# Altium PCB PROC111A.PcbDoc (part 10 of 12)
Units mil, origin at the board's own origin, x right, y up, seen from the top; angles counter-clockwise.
Board outline 7700 x 2300 mil, 6 copper layers (Top Layer, GND 1, SIG 1, SIG 2, GND 2, Bottom Layer), stack 61.062 mil thick; 841 components, 632 nets, 2914 pads, 1627 vias.
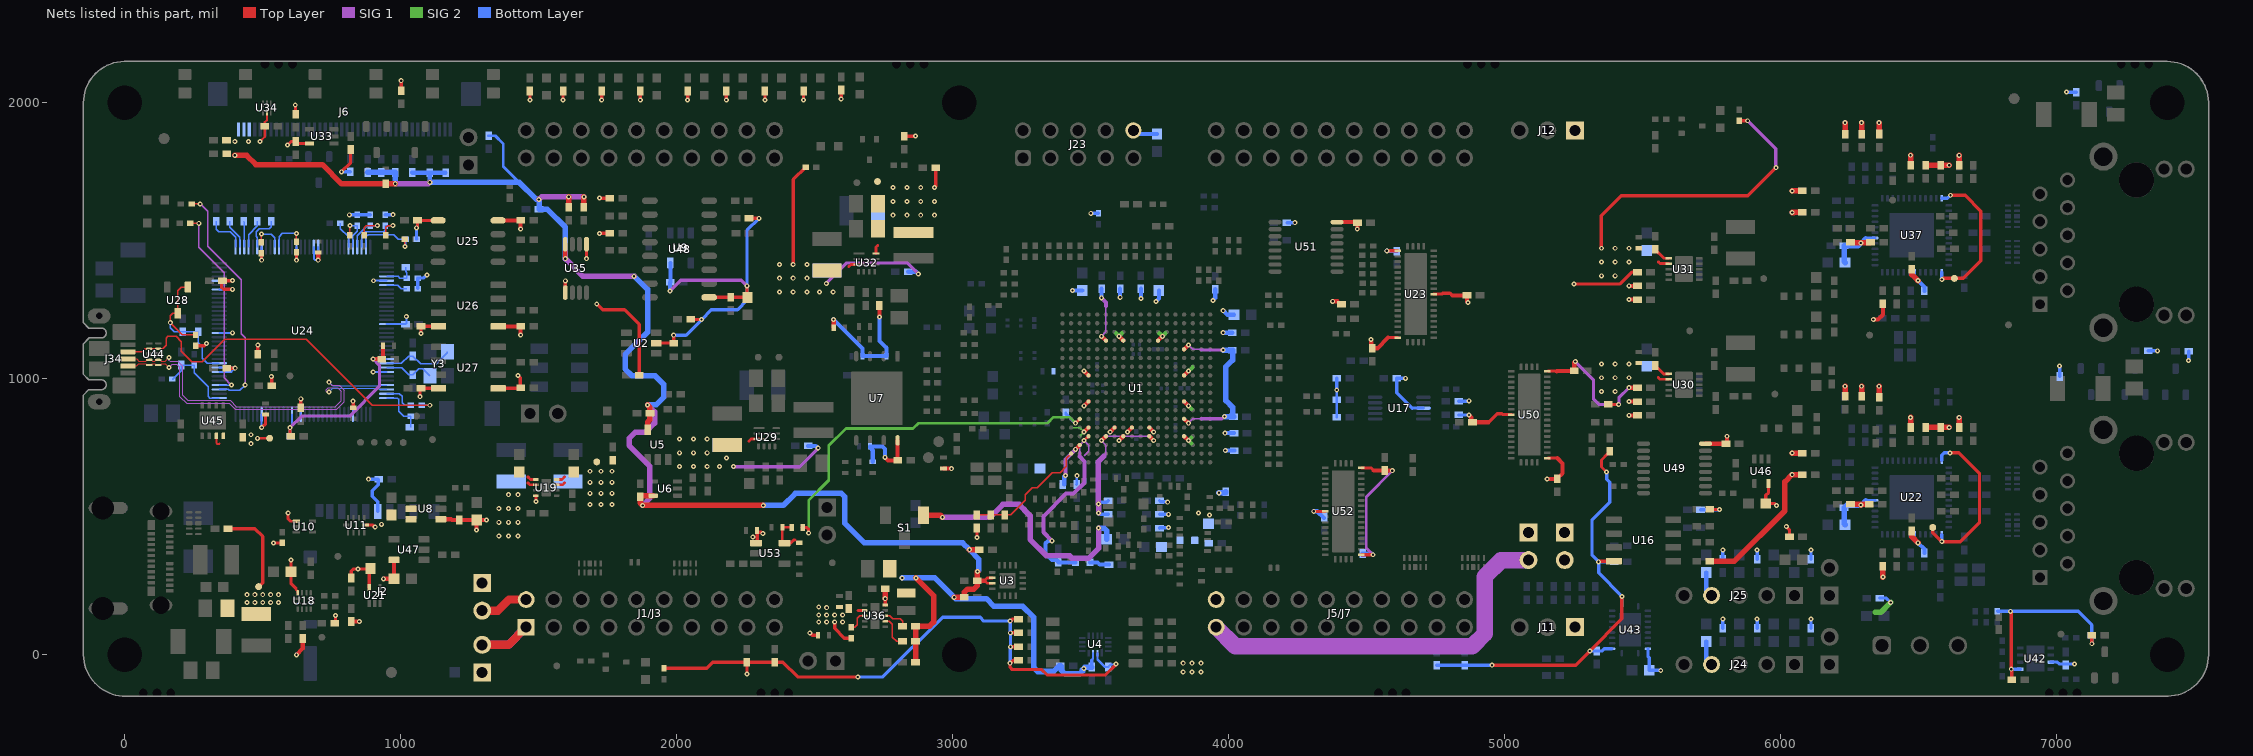
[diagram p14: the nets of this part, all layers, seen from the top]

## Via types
v1: diameter 18, hole 8, Top Layer to Bottom Layer, tented both sides, 1523 vias
v2: diameter 19.68, hole 7.87, Top Layer to Bottom Layer, tented both sides, 104 vias

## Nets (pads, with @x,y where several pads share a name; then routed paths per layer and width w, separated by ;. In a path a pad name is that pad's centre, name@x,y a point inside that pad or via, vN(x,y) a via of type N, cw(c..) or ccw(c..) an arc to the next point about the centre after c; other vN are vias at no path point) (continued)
VDD_XDS3V3: C139.2 C140.2 C141.2 C145.2 C146.1 C147.2 C148.1 C149.1 C150.2 C228.1 C232.1 C233.2 R138.2 R139.2 R140.2 R141.2 R142.2 R143.2 R144.2 R251.2 R311.2 R312.2 TP25.1 U24.7 U24.8 U24.16 U24.26 U24.28 U24.39 U24.47 U24.51 U24.52 U24.69 U24.79 U24.90 U24.101 U24.113 U24.122 U25.1 U26.8 U27.8 U45.3 U45.4 | length 1848.6
  Top Layer w7: U45.3@331.48,793.2 331.48,767.72 335.59,763.62 341.38,763.62 342.56,764.8 343.85,764.8
  Top Layer w8: v1(480.73,784.53) TP25.1@524.75,784.53
  Top Layer w12: R144.2@257.13,1120.19 287.58,1120.19 294.88,1127.49 v1(296.51,1127.49) ; C145.2@368.94,1038.47 v1(400,1038.47) ; v1(390,1324.16) 357.96,1324.16 350.19,1331.93 350.19,1355.66 C150.2@354.12,1355.66 v1(390,1355.66) ; R251.2@481.97,1088.85 v1(481.97,1122.33) ; R311.2@495,1455.31 495.54,1454.77 495.54,1430.41 v1(496.08,1429.87) ; v1(496.08,823.57) 510,837.49 C232.1@510,870.15 ; v1(530.73,1008.1) 530.73,1006.48 532.27,1004.94 C228.1@532.27,974.76 ; v1(622.07,1429.87) R312.2@622.07,1457.95 ; C147.2@637.63,894.84 v1(637.63,927.56) ; v1(826.42,918.87) 827.25,918.04 827.25,895.56 C146.1@827.49,895.32 ; v1(1056.61,1547.01) 1060.55,1550.94 C141.2@1060.55,1573.86 U25.1@1135.36,1573.86 ; v1(1069.48,935.27) 1069.48,965.27 U27.8@1136.73,965.27 ; v1(1073.41,1163.82) C140.2@1073.42,1190 U26.8@1136.73,1190
  Top Layer w15: v1(700.81,1429.87) C148.1@700.81,1457.63
  Bottom Layer w7: U24.7@342.35,1024.76 386.3,1024.76 v1(400,1038.47) 397.96,1040.51 U24.8@342.35,1040.51 ; U24.16@342.35,1166.5 v1@389.81,1166.5 ; U24.26@342.35,1323.98 v1@389.81,1323.98 ; U24.28@342.35,1355.47 v1@389.81,1355.47 ; v1@495.89,823.76 U24.122@495.89,871.22 ; v1@495.89,1430.06 U24.39@495.89,1477.52 ; v1@621.88,1430.06 U24.47@621.88,1477.52 ; U24.113@637.63,871.22 v1@637.63,918.68 ; U24.51@684.87,1477.52 684.87,1435.19 690,1430.06 v1@700.62,1430.06 ; U24.52@700.62,1477.52 v1@700.62,1430.06 ; v1(700.81,1429.87) v1@700.62,1430.06 ; U24.101@826.6,871.22 v1@826.6,918.68 ; v1@900,1024.76 U24.90@948.65,1024.76 ; v1@901.19,1355.47 U24.69@948.65,1355.47 ; U24.79@948.65,1197.99 C149.1@1016.88,1197.99 1020,1201.11 v1(1020,1225.91)
  Bottom Layer w8: v1@389.81,1166.5 v1(390,1166.68) ; v1@389.81,1323.98 v1(390,1324.16) ; v1@389.81,1355.47 v1(390,1355.66) ; v1@495.89,823.76 v1(496.08,823.57) ; v1@495.89,1430.06 v1(496.08,1429.87) ; v1@621.88,1430.06 v1(622.07,1429.87) ; v1@637.63,918.68 v1(637.63,927.56) ; v1(826.42,918.87) v1@826.6,918.68 ; v1(899.81,1024.58) v1@900,1024.76 ; v1(901,1355.28) v1@901.19,1355.47
  Bottom Layer w12: v1(813.57,1594.24) 813.7,1594.37 R141.2@842.24,1594.37 R140.2@889.13,1594.37 ; R139.2@943.35,1594.37 971.89,1594.37 v1(972.02,1594.5) ; v1(1056.61,1547.01) 1056.61,1507.08 R138.2@1057.31,1506.39 ; R143.2@1061.05,1326.93 R142.2@1061.05,1364.93 1061.41,1365.29 1083.79,1365.29 v1(1095,1376.5)
  other v1: 457.48,764.8 457.27,797.27
VDDA18_AM263_OSC_PLL: C38.1 FB2.2 U1.R4 | length 745.1
  Top Layer w10: v1(3475.87,776.1) U1.R4@3491.62,791.85
  SIG 1 w5: 3459.88,735.13 3459.88,760.11 v1(3475.87,776.1) 3491.87,760.11 3491.87,737.34 3476.37,721.84
  SIG 1 w8: 3459.88,717.9 3459.88,735.13
  SIG 1 w15: v1(3359.62,412.87) 3328.49,444 3328.49,501.77 3410.5,583.79 3437.94,583.79 3477.61,623.47 3477.61,665.87 3477.61,700.16 3459.88,717.9
  Bottom Layer w15: v1(3359.62,412.87) v1(3359.62,412.87) 3345.01,412.94 3336.22,404.15 3336.22,367.03 3359.62,343.63 3377.07,343.63 3381.39,339.32 C38.1@3381.39,336.02 3382.41,335 FB2.2@3444.44,335
VDDA_AM263_1V8_LDO: C33.1 C34.1 C35.1 C36.1 C37.1 FB2.1 S1.1 U1.R6 U1.R8 U1.R11 | length 1687.3
  Top Layer w15: v1(3538.87,776.1) U1.R6@3554.61,791.85 ; v1(3601.86,776.1) U1.R8@3617.61,791.85 ; U1.R11@3712.09,791.85 v1(3727.84,776.1)
  Top Layer w20: S1.1@2894.5,506.22 2954.45,506.22 v1(2962.52,498.15)
  SIG 1 w5: v1(3538.87,776.1) 3554.61,791.85 3617.61,791.85 ; 3548.11,719.25 3554.49,725.62 3554.49,760.48 ; v1(3601.86,776.1) 3617.61,791.85 ; v1(3727.84,776.1) 3712.09,791.85 3617.61,791.85
  SIG 1 w5.5: v1(3538.87,776.1) 3554.49,760.48
  SIG 1 w20: v1(2962.52,498.15) 3134.49,498.15 3181.38,545.04 3240.37,545.04 3258.68,526.73 3258.68,525.53 3280.39,503.82 3280.39,417.96 3339.4,358.94 3423.35,358.94 3432.84,349.45 3491.52,349.45 3528.01,385.94 v1(3528.01,458.97) ; v1(3527.6,545.88) 3527.6,700.24 3547.36,720 ; v1(3528.01,513.97) v1@3528.01,545.04
  Bottom Layer w12: v1(3527.6,545.88) 3529.22,545.88 3536.5,553.16 3556.94,553.16 C36.1@3562.76,558.97 ; v1(3528.01,513.97) 3533.01,508.97 C34.1@3562.76,508.97
  Bottom Layer w15: FB2.1@3497.59,335 3524.36,335 3532.56,326.8 C37.1@3565.75,326.8
  Bottom Layer w20: v1(3528.01,458.97) 3548.15,458.97 3557.39,449.73 C33.1@3557.39,419.08 ; v1(3964.49,587.04) 3987.63,587.04 3989.44,588.85 C35.1@3989.44,590.75
VDDA_AM263_3V3: C25.1 C26.1 C27.1 C28.1 FB1.2 U1.P7 U1.P9 U1.P11 | length 165.5
  Top Layer w15: v1(3570.36,807.6) U1.P7@3586.11,823.35 ; v1(3633.35,807.6) U1.P9@3649.1,823.35 ; U1.P11@3712.09,823.35 v1(3727.84,807.6)
  Bottom Layer w12: C26.1@3748.93,458.97 3749.84,459.88 3781.06,459.88 v1(3781.97,460.8) ; C27.1@3748.93,508.97 v1(3781.68,508.97) ; C28.1@3748.93,558.97 3753.73,554.17 3777.5,554.17 v1(3778.65,553.02)
VDDA_ETH1_1V8: TP7.1 U22.13 U22.48 | length 624.5
  Top Layer w12: TP7.1@6550.57,461.5 6550.82,461.24 6550.82,442.62 v1(6583.44,410) 6650.59,410 6720,479.41 6720,656.84 6645.28,731.56 v1(6612.73,731.56)
  Bottom Layer w12: v1(6583.44,410) U22.13@6583.44,436.18 ; U22.48@6583.44,703.9 6583.44,723.44 6591.56,731.56 v1(6612.73,731.56)
VDDA_ETH2_1V8: TP19.1 U37.13 U37.48 | length 545.8
  Top Layer w12: v1(6583.44,1360) 6587.35,1363.91 TP19.1@6629.03,1363.91 6661.27,1363.91 6725,1427.64 6725,1607.84 6667.84,1665 v1(6615,1665)
  Bottom Layer w12: v1(6583.44,1360) U37.13@6583.44,1386.18 ; U37.48@6583.44,1653.9 6603.9,1653.9 v1(6615,1665)
VDDC_XDS_1V0: C153.2 C154.2 C155.2 C156.1 U24.87 U24.115 | length 741.4
  Top Layer w12: v1(598.48,823) 598.48,794.73 C155.2@601.36,791.85
  Top Layer w15: v1(899.81,1071.82) 899.97,1071.67 931.29,1071.67 C153.2@931.38,1071.57 935,1075.2 C156.1@935,1120
  SIG 1 w12: v1(598.48,823) 640.48,865 815,865 922.69,972.69 922.69,1048.95 v1(899.81,1071.82)
  Bottom Layer w7: v1(598.48,823) 606.13,830.65 U24.115@606.13,871.22 ; v1@900,1072.01 U24.87@948.65,1072.01
  Bottom Layer w8: v1(899.81,1071.82) v1@900,1072.01
  Bottom Layer w12: v1(598.48,823) 598.48,794.73 C154.2@601.36,791.85
VDDS_AM263_LDO_1V8: C14.1 C15.1 C16.1 C17.1 C18.1 C98.1 U1.D6 U1.E15 U1.L4 U1.N15 U1.T3 | length 1043.1
  Top Layer w15: v1(3444.38,744.61) U1.T3@3460.12,760.35 ; v1(3475.87,902.09) U1.L4@3491.62,917.83 ; v1(3538.87,1154.06) U1.D6@3554.61,1138.31 ; U1.N15@3838.08,854.84 v1(3853.83,839.09) ; U1.E15@3838.08,1106.81 v1(3853.83,1122.56)
  SIG 1 w4.75: v1(3538.87,1154.06) 3554.99,1170.18 3554.99,1264.29 ; v1(3853.83,839.09) 3869.95,855.22 3891.69,855.22 3892.07,855.59 3900,855.59 ; v1(3853.83,1122.56) 3869.57,1106.82 3896.43,1106.82 3899.19,1104.06
  SIG 1 w12: 3899.19,1104.06 v1(3979.81,1104.06) ; 3900,855.59 3975.13,855.59 3982.86,863.32 v1(3984.48,863.32)
  SIG 1 w15: v1(3407.88,650.12) 3407.88,708.11 v1(3444.38,744.61) ; v1(3538.87,1293.54) 3538.87,1292.72 3554.99,1276.6 3554.99,1264.29
  Bottom Layer w15: C15.1@3403.63,617.37 3403.63,645.87 v1(3407.88,650.12) ; v1(3538.87,1293.54) C16.1@3538.87,1326.28
  Bottom Layer w20: v1(3979.81,1104.06) C18.1@4012.56,1104.06 ; v1(3984.48,863.32) C17.1@4017.23,863.32 4015.62,863.32 4013.81,865.13 4013.81,896.85 3989.63,921.03 3989.63,1043.88 4013.81,1068.06 C18.1@4013.81,1103.17
VPP_AM263_1V7: C253.1 R372.2 R376.2 U53.5 | length 125.2
  Top Layer w10: C253.1@2381.93,450.2 2381.93,411.78 2388.74,404.97 U53.5@2389.8,404.97 2413.02,404.97 2423.82,415.77 2428.32,415.77 ; C253.1@2383.56,461.96 2415.46,461.96 R376.2@2416.29,461.13
VPP_AM263_1V7_R: C250.1 R376.1 U1.N3 | length 1409
  Top Layer w10: v1(3444.38,839.09) U1.N3@3460.12,854.84
  Top Layer w12: R376.1@2455,462.42 R376.1@2456.29,461.13 2470.86,461.13 2477.35,454.64 2477.35,441.54 v1(2477.89,441) v1@2476.27,441
  SIG 2 w10: v1(2477.89,441) 2477.89,559.65 2550.6,632.35 2550.6,757.83 2612.76,820 2855.91,820 2875,839.09 3342.53,839.09 3364.41,860.97 3422.5,860.97 v1(3444.38,839.09)
  Bottom Layer w10: C250.1@3409.37,877.28 3409.37,873.34 3421.75,860.97 3421.94,860.97 3443.82,839.09 v1(3444.38,839.09)
VSD_3V3: C67.1 C71.2 J2.4 U8.5 U8.6 U10.1 U11.10 | length 258.3
  Top Layer w10: v1@591.69,513.17 591.69,493.06 600.76,483.99 621.54,483.99 U10.1@621.63,483.9
  Top Layer w12: U11.10@873.63,470 898.43,470 905.54,462.89 v1(907.17,462.89)
  Bottom Layer w12: v1@882.67,635.81 917.73,635.81 918.11,635.43 918.11,616.13 897.13,595.14 897.13,573.87 916.06,554.93 J2.4@916.06,519.61
  other v1: 929.71,472.8 591.99,513.48 882.45,636.24
VSYS_3V3: C4.1 C5.1 C6.1 C7.1 C8.1 C9.1 C10.1 C11.1 C12.1 C13.1 C23.1 C24.1 C43.2 C57.2 C62.2 C66.2 C68.1 C69.1 C70.2 C99.2 C100.2 C111.2 C128.1 C129.1 C130.1 C131.1 C132.1 C133.1 C136.2 C137.2 C138.2 C169.1 C170.1 C171.1 C181.2 C182.2 C205.1 C206.1 C207.1 C208.1 C209.1 C210.1 C213.1 C223.2 C226.2 C236.1 C237.1 C238.2 C239.2 C240.2 C241.2 C242.2 C243.2 C244.2 C245.2 C246.2 C248.1 FB1.1 J9.1 J12.1 J13.1 J23.10 L3.2 R14.1 R15.1 R16.1 R17.1 R31.2 R40.2 R41.2 R55.2 R56.2 R63.2 R64.2 R73.2 R74.2 R108.2 R109.2 R110.2 R111.2 R112.2 R113.2 R114.2 R115.2 R116.2 R147.2 R155.2 R162.2 R175.2 R176.2 R177.2 R178.2 R179.2 R181.2 R203.2 R204.2 R205.2 R206.2 R207.2 R208.2 R209.2 R210.2 R211.2 R224.1 R226.2 R228.2 R230.1 R232.2 R234.2 R244.2 R258.2 R262.2 R263.2 R264.2 R266.2 R267.2 R268.2 R269.1 R270.1 R271.1 R273.2 R277.2 R279.2 R287.1 R288.1 R291.1 R292.1 R295.2 R296.2 R298.1 R301.2 R305.1 R306.1 R313.2 R314.2 R318.1 R319.1 R320.1 R336.2 R337.2 R338.2 R339.2 TP9.1 U1.D8 U1.D12 U1.H4 U1.H15 U1.L15 U1.P4 U1.R15 U2.5 U4.2 U7.8 U8.1 U9.5 U16.8 U17.8 U22.18 U22.30 U23.1 U23.17 U23.30 U25.8 U26.1 U27.1 U32.3 U33.5 U34.5 U35.1 U35.5 U37.18 U37.30 U42.5 U43.2 U43.10 U46.5 U48.1 U49.16 U50.1 U50.17 U50.30 U51.16 U52.1 U52.17 U52.30 | length 15009.5
  Top Layer w6: 515,1937.06 U34.5@515,1965.47
  Top Layer w8: v1(490,1860) 507.31,1877.31 C181.2@507.31,1915 507.31,1929.37 515,1937.06
  Top Layer w10: U32.3@2722.01,1453.83 2722.01,1477.63 2728.37,1484 ; v1(5368.46,662.43) 5350.14,680.76 5350.14,706.13 5371.18,727.18 5373.19,727.18 5380,733.99 R287.1@5380,737.92
  Top Layer w11: v1(590,1847.56) 590.33,1847.56 602.88,1860.11 618.69,1860.11 C182.2@619.3,1859.5 619.3,1858.87 625.61,1852.56 U33.5@669.08,1852.56 ; v1(4307.78,520) U52.30@4350.04,520 ; U52.1@4479.96,362.52 v1(4522.27,362.52) ; U52.17@4479.96,677.48 4515.02,677.48 4524.94,667.56 ; 4577.19,1149.02 U23.17@4612.24,1149.02 ; v1@4577.19,1463.98 U23.1@4612.24,1463.98 ; U23.30@4742.17,1306.5 4772.54,1306.5 4775.72,1309.69 ; 4968.5,870.04 4971.84,873.38 4990,873.38 4993.35,870.04 U50.30@5023.43,870.04 ; U50.1@5156.3,712.56 5190,712.56 ; U50.17@5156.3,1027.52 5185,1027.52
  Top Layer w12: v1(539.29,405.16) R40.2@570.7,405.16 ; v1(617.59,1991.63) 618.34,1990.88 618.34,1951.73 R179.2@619.09,1950.98 ; v1(785,1750) 818.08,1783.08 R178.2@818.08,1830.9 ; R181.2@1001.5,2043.62 v1(1001.5,2080) ; U27.1@1353.27,965.27 1432.29,965.27 1432.29,1003.83 v1(1424.25,1011.86) ; v1(1467.87,2010) R279.2@1467.87,2042.56 ; v1(1587.87,2010) R277.2@1587.87,2042.56 ; U35.1@1595.98,1312.4 v1(1595.98,1355.17) ; v1(1672.76,1435.32) U35.5@1672.76,1487.6 ; v1(1710,1271.26) 1731.26,1250 1810.66,1250 1863.62,1197.03 R295.2@1863.62,1013.59 ; v1(1720,1526.88) R270.1@1757.31,1526.88 ; v1(1720,1654.54) R271.1@1757.31,1654.54 ; v1(1727.87,2010) R273.2@1727.87,2042.56 ; v1(1867.87,2010) R267.2@1867.87,2042.56 ; U2.5@1925.37,1129.45 C57.2@1988.78,1129.45 v1(1988.78,1158.13) ; R314.2@1953.52,-48.42 2109.16,-48.42 2130.33,-27.24 R55.2@2254.17,-27.24 ; v1(2039.29,2010) R266.2@2039.29,2042.56 ; R296.2@2050.03,1215 2089.7,1215 v1(2090,1214.7) ; U48.1@2117.28,1295 C237.1@2195.94,1295 C236.1@2255.95,1295 2254.17,1296.77 v1(2254.17,1336.82) ; v1(2179.29,2010) R264.2@2179.29,2042.56 ; v1(2254.17,-70) R55.2@2254.17,-27.24 ; R269.1@2261.63,1581.55 v1(2298.33,1581.55) ; v1(2319.29,2010) R263.2@2319.29,2042.56 ; v1(2459.29,2010) R262.2@2459.29,2042.56 ; v1(2595.47,2013.94) R313.2@2595.47,2046.5 ; v1(2655.91,-80.32) 2437.43,-80.32 2384.36,-27.24 R56.2@2354.17,-27.24 R55.2@2254.17,-27.24 ; R258.2@2824.53,1879.19 2864.19,1879.19 v1(2865,1880) ; v1(2933.86,1692.84) 2938.62,1697.6 R268.2@2938.62,1765.46 ; v1(3207.9,122.3) 3209.52,122.3 3217.21,129.99 3237.83,129.99 R17.1@3238.31,129.51 ; v1(3208.42,79.62) 3208.47,79.56 3238.25,79.56 R16.1@3238.31,79.51 ; v1(3209.44,28.94) 3209.73,29.22 3238.02,29.22 R15.1@3238.31,29.51 ; R14.1@3238.31,-20.49 3237.17,-19.36 3219.84,-19.36 3208.7,-30.49 v1(3207.56,-30.49) 3207.56,-45.88 3215.04,-53.37 3322.12,-53.37 3341.94,-73.19 3552.23,-73.19 v1(3591.61,-33.82) ; 4775.72,1309.69 4775.88,1309.84 4801.65,1309.84 4810,1301.49 ; 4941.28,842.82 4968.5,870.04 ; v1(4953.12,-37.59) 5256.81,-37.59 v1(5308.06,13.66) 5424.13,129.73 v1(5424.13,211.28) ; v1(5250.83,1343.61) 5417.49,1343.61 5460.7,1386.82 R155.2@5480.51,1386.82 ; v1(5340,337.03) 5342.11,339.14 U16.8@5395.51,339.14 ; R292.1@5375,907.02 5412.09,907.02 v1(5412.51,906.6) ; R320.1@5742.56,526.73 v1(5777.62,526.73) ; U46.5@5955.59,620.71 5955.59,587.98 5945.59,577.98 C248.1@5945.59,548.38 5976.43,548.38 v1(5984.31,540.5) ; v1@6835,155 v1(6832.5,157.5) 6832.5,155.88 6835,153.38 v1(6835,-52.2) 6835,-53.82 6836.38,-55.2 C226.2@6836.38,-89.6 ; v1(7126.76,40) R226.2@7126.76,71.46
  Top Layer w15: U8.1@1145.16,491.19 1181.92,491.19 1185,488.11 1212.05,488.11 C69.1@1212.1,488.16 C68.1@1274.76,488.16 ; v1(1274.76,452.5) C68.1@1274.76,488.16 ; C68.1@1274.76,490.16 C68.1@1274.76,488.16 ; v1(1310.42,488.16) C68.1@1274.76,488.16 ; U25.8@1352.36,1573.86 C138.2@1434.25,1573.86 v1@1434.25,1542.7 ; U26.1@1353.27,1190 C137.2@1434.25,1190 v1@1434.25,1158.83 ; R336.2@2568.43,1184.92 v1@2568.43,1214.24 ; R162.2@2734,1265.68 2734,1223.93 v1(2734.18,1223.76) ; v1(2754.17,715.58) 2765.61,704.15 C66.2@2800,704.15 U7.8@2800,776.92 ; R301.2@2966.47,674.56 2994.88,674.56 v1(2995.01,674.44) ; v1(3475.87,807.6) U1.P4@3491.62,823.35 ; v1(3475.87,1028.07) U1.H4@3491.62,1012.32 ; v1(3601.86,1154.06) U1.D8@3617.61,1138.31 ; U1.D12@3743.59,1138.31 v1(3759.34,1154.06) ; U1.R15@3838.08,791.85 v1(3853.83,776.1) ; U1.L15@3838.08,917.83 v1(3853.83,902.09) ; U1.H15@3838.08,1012.32 v1(3853.83,1028.07) ; v1@4377.11,1280.83 4394.25,1280.83 4404.17,1270.9 R288.1@4408.11,1270.9 ; U51.16@4392.2,1567.48 4466.18,1567.48 4465.79,1567.09 4465.79,1543.06 v1(4465.41,1542.67) ; v1(4515.02,1142.76) 4515.6,1142.19 4515.6,1131.75 4516.07,1131.28 4516.07,1114.78 C240.2@4520.38,1110.47 4538.64,1110.47 4577.19,1149.02 ; 4524.94,667.56 C245.2@4565,667.56 4565.22,667.34 4592.34,667.34 v1(4592.56,667.13) ; 4810,1301.49 C242.2@4863.22,1301.49 ; C242.2@4862.76,1301.95 C242.2@4863.22,1301.49 ; v1(4866.7,1276.95) 4863.22,1280.43 C242.2@4863.22,1301.49 ; v1(4869.79,868.97) 4869.79,868.15 4878.69,859.26 4878.69,842.82 C111.2@4882.62,842.82 4941.28,842.82 ; v1(5153.59,637.43) 5188.92,637.43 C239.2@5189.88,638.39 5209.07,657.58 5209.07,693.49 5190,712.56 ; 5188.41,1027.52 5189.58,1028.69 C238.2@5251.38,1028.69 5251.38,1058.68 v1(5255.31,1062.62) ; v1(5450,967.63) R147.2@5480.51,967.63 ; U49.16@5727.2,764.8 C43.2@5801.38,764.8 5805.31,768.73 v1(5805.31,791.85) ; v1(6335.13,1214.7) 6352.57,1214.7 6370,1232.14 R209.2@6370,1271.38
  Top Layer w20: R318.1@5742.56,338.21 5831.22,338.21 6015,522 6015,626.17 v1(6041.38,652.54) 6041.49,652.65 R108.2@6077.68,652.65 ; v1@6046.38,730.85 v1(6041.38,730.85) 6041.49,730.96 R109.2@6077.76,730.96 ; v1@6046.38,1602.54 v1(6041.38,1602.54) 6041.49,1602.65 R203.2@6077.76,1602.65 ; v1@6046.38,1680.85 v1(6041.38,1680.85) 6041.49,1680.96 R204.2@6077.76,1680.96 ; v1@6232.9,967.97 v1(6232.9,972.97) 6233.01,972.86 R115.2@6233.01,936.58 ; v1(6232.9,1927.97) 6233.01,1927.86 R210.2@6233.01,1886.59 ; C133.1@6252.76,545.04 6287.44,545.04 v1(6290,542.48) 6292.56,545.04 C132.1@6320.32,545.04 ; C210.1@6252.76,1495.04 6255.32,1492.48 v1(6290,1492.48) 6322.76,1492.48 C209.1@6325.32,1495.04 ; v1@6292.9,967.97 v1(6292.9,972.97) 6293.01,972.86 R116.2@6293.01,936.59 ; v1(6292.9,1927.97) 6293.01,1927.86 R211.2@6293.01,1886.59 ; v1@6356.17,968.05 v1(6356.17,973.05) 6356.28,972.94 R113.2@6356.28,936.67 ; v1(6356.17,1928.05) 6356.28,1927.94 R205.2@6356.28,1886.67 ; v1(6370,281.38) 6369.24,281.38 6370,282.14 R114.2@6370,321.38 ; R305.1@6470,823.7 v1(6470,860) ; R306.1@6470,1773.7 v1(6470,1810) ; C130.1@6475,446.85 6475,427.72 v1(6497.07,405.66) ; C207.1@6475,1396.85 6475,1377.72 v1(6497.07,1355.66) ; R112.2@6524.39,823.7 v1(6610,823.7) ; R207.2@6524.39,1773.7 R208.2@6579.39,1773.7 v1(6610,1773.7) ; R111.2@6646.28,823.31 v1(6646.28,859.61) ; R206.2@6646.28,1773.31 v1(6646.28,1809.61)
  SIG 1 w10: v1(4522.27,362.52) 4497.86,386.92 4497.86,572.43 v1(4592.56,667.13)
  SIG 1 w12: v1(1975.77,1318.62) 2014.6,1357.46 2233.54,1357.46 v1(2254.17,1336.82) ; v1(5255.31,1062.62) 5321.05,996.88 5321.05,927.3 5341.75,906.6 v1(5412.51,906.6) 5413.65,907.75 5413.65,931.29 v1(5450,967.63)
  SIG 2 w5.3: 3436.54,823.25 3460.22,823.25 v1(3475.87,807.6) 3460.22,791.95
  SIG 2 w15: 3590.76,1165.16 v1(3601.86,1154.06) 3612.96,1165.16 ; 3748.24,1165.16 v1(3759.34,1154.06) 3770.44,1165.16 ; v1(3853.83,902.09) 3864.93,890.98 ; v1(3853.83,1028.07) 3854.64,1028.07 3868.18,1041.61 ; 3864.93,765 v1(3853.83,776.1) 3864.93,787.2
  Bottom Layer w7: 3523.95,-16.88 U4.2@3523.95,6.28
  Bottom Layer w8: 3523.95,-16.88 3551.47,-44.4 C62.2@3563.69,-44.4 3563.69,-43.35 3571.5,-35.54 3589.89,-35.54 v1(3591.61,-33.82)
  Bottom Layer w10: C7.1@3448.63,617.37 3449.44,618.18 3449.44,648.28 v1(3450.25,649.09) ; R73.2@4391.17,860.55 R74.2@4391.17,924.9 v1(4391.17,959.9) ; 4664.68,893.75 U17.8@4705.28,893.75 ; 6307.72,560.2 U22.30@6341.32,560.2 ; 6307.72,1510.2 U37.30@6341.32,1510.2 ; 6485.02,417.71 U22.18@6485.02,436.18 ; 6485.02,1367.71 U37.18@6485.02,1386.18
  Bottom Layer w12: v1(785,1750) R177.2@816.87,1750 ; v1(1988.78,1158.13) 2033.43,1158.13 v1(2090,1214.7) 2125.3,1250 2220,1250 2254.17,1284.17 v1(2254.17,1336.82) 2254.17,1537.4 v1(2298.33,1581.55) ; v1(2655.91,-80.32) 2746.77,-80.32 2962.78,135.7 3099.21,135.7 3112.61,122.3 v1(3207.9,122.3) 3208.16,122.04 3208.16,79.88 3208.93,79.11 3208.93,29.45 v1(3209.44,28.94) 3208.5,28 3208.5,-29.55 v1(3207.56,-30.49) ; v1(3433.43,1319.95) v1@3433.47,1320 ; v1(3499.94,1599.69) R41.2@3528.01,1599.69 ; R298.1@4212.13,1565.49 v1(4239.19,1565.49) ; v1(4391.17,959.9) 4391.38,960.11 R291.1@4391.38,1002.36 ; v1(4640.08,1001.68) 4639.89,1001.87 4608.81,1001.87 C100.2@4608.62,1002.06 4608.62,949.81 4664.68,893.75 ; R175.2@4753.31,-37.59 R176.2@4854.17,-37.59 v1(4953.12,-37.59) ; R63.2@4832.83,869.06 4869.7,869.06 v1(4869.79,868.97) ; R64.2@4832.83,918.43 4867.89,918.43 v1(4869.79,920.34) ; v1(5308.06,13.66) C223.2@5333.66,13.66 5351.94,13.66 5360,21.73 U43.2@5388.7,21.73 ; v1(5368.46,662.43) 5369.61,661.28 5369.61,636.29 5380,625.91 5380,552.8 5316.14,488.94 5316.14,360.9 v1(5340,337.03) ; C99.2@5396.38,337.03 v1(5340,337.03) ; U43.10@5424.13,175.27 v1(5424.13,211.28) 5424.13,212.9 5340,297.03 v1(5340,337.03) ; R319.1@5708.93,525 5775.89,525 v1(5777.62,526.73) ; v1(6832.5,157.5) 6785.26,157.5 R244.2@6785,157.24 7077.76,157.24 7126.76,108.25 R228.2@7126.76,71.46 v1(7126.76,40) ; v1(6835,-52.2) 6835.27,-51.93 U42.5@6867.68,-51.93 ; R224.1@7010.2,1008.62 v1(7010.2,1045.94) ; v1(7035,2039.61) 7035.98,2038.62 R230.1@7070,2038.62 ; R232.2@7331.11,1101.28 v1(7365,1101.28) ; v1(7477.57,1066.11) R234.2@7477.57,1100
  Bottom Layer w15: v1(1975.77,1318.62) C70.2@1975.77,1350 1976.56,1350.8 U9.5@1976.56,1420.16 ; v1(2568.16,1214.74) 2673.04,1109.86 R338.2@2673.04,1082.25 R337.2@2759.53,1082.25 2759.53,1112.24 2734.18,1137.59 v1(2734.18,1223.76) ; R339.2@2710,699.28 2710,740.81 2700.31,750.5 R31.2@2700.31,755 2745,755 2753.79,746.21 2753.79,715.97 v1(2754.17,715.58) ; v1@3433.47,1320 C6.1@3469.13,1320 ; C10.1@3606.08,1326.28 3606.37,1325.99 v1(3606.37,1295.16) ; J23.10@3654.17,1900 3667.5,1886.67 3700,1886.67 3700.17,1886.5 C213.1@3740,1886.5 ; v1(3681.66,1290.59) C11.1@3681.66,1326.28 ; v1(3736.11,1280.04) 3746.79,1290.72 3746.79,1319.78 C5.1@3746.57,1320 ; v1(3942.96,1284.14) 3942.96,1284.96 3950.67,1292.66 C12.1@3950.67,1324.6 ; v1(3979.81,1167.07) C13.1@4012.56,1167.07 ; v1(3979.81,1246.81) 3994.81,1231.81 C4.1@4018.5,1231.81 ; v1(3985.81,802.97) C8.1@4018.56,802.97 ; v1(3987.3,740) C9.1@4020.05,740 ; v1(4307.78,520) 4320.23,520 C243.2@4345.23,495 ; C244.2@4485,366.83 4517.96,366.83 v1(4522.27,362.52) ; v1(4572.39,1463.79) 4573.2,1463.79 4574.38,1462.61 C241.2@4608.25,1462.61 ; v1(6290,542.48) 6307.72,560.2 ; v1(6290,1492.48) 6307.72,1510.2 ; 6485.02,417.71 v1(6497.07,405.66) 6520,382.72 C131.1@6520,368.62 ; 6485.02,1367.71 v1(6497.07,1355.66) 6520,1332.72 C208.1@6520,1318.62
  Bottom Layer w20: C128.1@6232.85,471.24 6229.14,474.96 C129.1@6229.14,531.97 6239.65,542.48 v1(6290,542.48) ; C205.1@6232.85,1421.24 6229.14,1424.96 C206.1@6229.14,1481.97 6279.48,1481.97 v1(6290,1492.48)
  other v1: 3930.3,506.19 3890.09,513.64 1434.23,1158.81 4376.3,1280.83 1434.23,1542.68 2783.86,1592.84 2833.86,1592.84 2883.86,1592.84 2933.86,1592.84 2783.86,1642.84 2833.86,1642.84 2883.86,1642.84 2933.86,1642.84 2783.86,1692.84 2833.86,1692.84 2883.86,1692.84
VSYS_3V3_BP: J1/J3.1 J5/J7.41 J9.2 J13.2 | length 1781.6
  Top Layer w30: J9.2@1295,36.05 1390.23,36.05 J1/J3.1@1454.17,100
  SIG 1 w30: J9.2@1295,36.05 1390.23,36.05 J1/J3.1@1454.17,100
  SIG 1 w60: J5/J7.41@3954.17,100 3954.45,100 4022.83,31.61 4882.5,31.61 4927.41,76.52 4927.41,283.4 4986.31,342.3 5084.88,342.3 J13.2@5085.83,343.25
VSYS_5V0: C107.1 C108.1 C161.1 C162.1 C163.1 C167.1 C168.1 C172.1 C173.1 C174.1 C179.1 C180.1 C211.1 C212.1 C224.1 C225.2 C254.1 J11.1 J24.4 J25.4 R1.2 R146.2 R149.1 R150.1 R156.2 R157.1 R158.1 R236.2 R237.2 R238.2 R239.2 R240.2 R241.2 R242.2 R243.2 R257.2 R265.2 R302.2 R374.2 TP8.1 U19.7 U19.8 U29.6 U30.1 U30.2 U31.1 U31.2 U32.6 U42.3 U43.19 U53.1 | length 3599.1
  Top Layer w10: U19.7@1564.33,615.75 1586.08,615.75 1593.85,623.51 ; U19.8@1564.33,635.43 1584.28,635.43 1593.85,645 ; 2261.63,773.91 2269.56,781.84 U29.6@2298.33,781.84 ; 2623.3,1406.53 2631.23,1414.46 U32.6@2660,1414.46 ; C163.1@5545.21,1048.48 5575.89,1017.8 U30.1@5594.01,1017.8 ; C174.1@5545.21,1467.67 5575.89,1436.99 U31.1@5594.01,1436.99 ; 5555.96,1005 5562.84,998.12 U30.2@5594.01,998.12 ; 5555.96,1424.19 5562.84,1417.31 U31.2@5594.01,1417.31
  Top Layer w12: U53.1@2287.43,404.97 2291.19,408.72 C254.1@2291.19,446.9 ; C254.1@2291.19,450.13 C254.1@2291.19,446.9 ; v1(2311.7,439.92) 2310.08,439.92 2305.86,444.13 2292.69,444.13 2291.19,445.63 C254.1@2291.19,446.9 ; v1(2421.67,1414.46) 2421.67,1722.39 R265.2@2466.4,1767.12 ; v1(2481.98,78.49) 2483.61,78.49 2490.91,71.19 R374.2@2511.35,71.19 ; v1(3087.35,425.17) 3087.47,425.29 R1.2@3087.47,459.62 ; v1(5350,1473.02) 5350,1591.6 5421.97,1663.56 5881.06,1663.56 v1(5982.5,1765) ; R302.2@5850,1934.58 5850.42,1935 v1(5880,1935) ; v1(6020,465) 6031.38,453.62 R243.2@6031.38,428.2
  Top Layer w15: v1(5450,867.63) R149.1@5480.51,867.63 ; v1(5450,917.63) R150.1@5480.51,917.63 ; v1(5450,1286.82) R157.1@5480.51,1286.82 ; v1(5450,1336.82) R158.1@5480.51,1336.82
  SIG 1 w12: v1(2205,681.84) 2445.25,681.84 v1(2512.21,748.8) ; v1(2541.67,1345.48) 2615.94,1419.74 2835.26,1419.74 v1(2875,1380) ; v1(5880,1935) 5981.35,1833.65 5981.35,1766.15 v1(5982.5,1765)
  SIG 2 w20: 6342.17,153.97 6362.09,153.97 v1(6398.12,190)
  Bottom Layer w12: U43.19@5518.62,21.73 5518.62,-5 5523.54,-9.92 C224.1@5523.54,-56.53 v1(5565,-56.53) ; R238.2@5790,95.75 v1(5790,130) ; R241.2@5790,345.75 v1(5790,380) ; R237.2@5914.18,95.75 v1(5914.18,130) ; R240.2@5914.18,345.75 v1(5914.18,380) ; R236.2@6109.18,95.75 v1(6109.18,130) ; R239.2@6109.18,345.75 v1(6109.18,380) ; R242.2@6358.76,205.53 6382.59,205.53 v1(6398.12,190) ; U42.3@6977.91,-26.34 7001.15,-26.34 7008.04,-33.23 v1(7063.78,-33.23)
  Bottom Layer w15: R146.2@2475.95,756.68 2503.52,756.68 2511.4,748.8 v1(2512.21,748.8) ; R156.2@2838.74,1387.88 2866.3,1387.88 2874.19,1380 v1(2875,1380) ; C211.1@5730,48.5 5730,-15.82 J24.4@5749.18,-35 ; C212.1@5730,298.5 5730,234.18 J25.4@5749.18,215
  other v1: 2275.43,427.17 1685,545 1725,545 1765,545 1685,585 1725,585 1765,585 1685,625 1725,625 1765,625 1685,665 1725,665 1765,665 2010,681.84 2060,681.84 2110,681.84 2155,681.84 2180,712.86 2010,731.84 2060,731.84 2110,731.84 2010,781.84 2060,781.84 2110,781.84 5350,953.83 5400,953.83 5350,1003.83 5400,1003.83 5450,1003.83 5350,1053.83 5400,1053.83 5450,1053.83 2371.67,1314.46 2421.67,1314.46 2471.67,1314.46 2516.67,1314.46 2566.67,1314.46 2371.67,1364.46 2421.67,1364.46 2471.67,1364.46 5350,1373.02 5400,1373.02 2371.67,1414.46 2471.67,1414.46 5350,1423.02 5400,1423.02 5450,1423.02 5400,1473.02 5450,1473.02
VSYS_5V0_BP_1: J1/J3.21 J10.2 | length 175.7
  Top Layer w30: J10.2@1295,160 1352.31,160 1392.31,200 J1/J3.21@1454.17,200
VSYS_5V0_BP_2: J5/J7.61 J14.2
  other v1: 3834.6,-62.74 3866.84,-62.74 3899.09,-62.74 3834.6,-30.49 3866.84,-30.49 3899.09,-30.49
VSYS_MON_AM263_: C48.1 R1.1 R2.2 U1.U2 | length 462
  Top Layer w5.3: R1.1@3087.47,506.87 C48.1@3137.47,506.87 R2.2@3187.66,506.87 3210.84,506.87 3263.31,559.33 3263.31,579.66 3288.09,604.45 3305.73,604.45 3360.94,659.66 3388.51,659.66 3411.66,682.81 3411.66,711.89 U1.U2@3428.63,728.86
VSYS_TA_3V3: C60.2 C61.2 C64.2 C65.2 C183.2 C184.2 C185.1 C186.1 J6.1 J6.2 J6.3 L4.2 R8.1 R10.1 R11.1 R182.1 R183.1 R184.1 R185.1 R186.1 R187.1 R188.1 R189.2 R190.2 R191.2 R192.2 R194.2 R195.2 R315.2 U3.14 U3.15 U4.3 U5.5 U6.5 U35.8 U36.10 | length 7071.8
  Top Layer w10: 3113.33,268.33 3115,270 ; U3.15@3142.94,258.86 3126.14,258.86 3115,270 ; U3.14@3142.94,278.54 3123.54,278.54 3115,270
  Top Layer w12: U36.10@2755.12,180.44 v1(2755.12,203.41)
  Top Layer w15: v1(1595.98,1435.32) U35.8@1595.98,1487.6 ; C60.2@3088.62,268.33 3113.33,268.33
  Top Layer w20: v1(398.65,1809.61) 441.39,1809.61 474.83,1776.17 715.89,1776.17 785.68,1706.38 R184.1@944.86,1706.38 979.33,1706.38 v1(979.84,1706.89) ; R192.2@1608.28,1621.97 v1(1608.28,1659.27) ; R190.2@1663.28,1621.97 v1(1663.28,1659.27) ; U5.5@1893.91,815.53 1893.91,842.9 1902.85,851.83 C65.2@1902.85,874.86 1902.85,896.62 v1(1893.91,905.56) ; U6.5@1914.38,576.8 1867.57,576.8 C64.2@1867.57,572.86 1867.65,572.78 1867.65,550.15 v1(1876.56,541.23) v1(2313.34,541.23) ; v1(2755.12,203.41) C186.1@2755.12,239.37 ; R315.2@2865.12,-26.59 R195.2@2865.12,48.66 R194.2@2865.12,103.66 2915.59,103.66 2930.35,118.43 2930.35,214.55 v1(2866.5,278.41) ; v1(3005,208.27) 3005.31,208.58 R10.1@3041.38,208.58 3041.38,225.86 3053.78,238.27 3076.3,238.27 3088.01,249.98 3088.01,267.72 C60.2@3088.62,268.33 3088.62,300.5 v1(3089.58,301.46) ; v1(3060,380.76) R11.1@3096.38,380.76
  SIG 1 w20: v1(979.84,1706.89) 1100,1706.89 v1(1105,1711.89) ; v1(1500,1650) 1500.75,1650 1510.03,1659.27 v1(1608.28,1659.27) v1(1663.28,1659.27) ; v1(1595.98,1435.32) 1660.08,1371.22 v1(1845,1371.22) ; v1@1876.95,541.62 1901.87,566.54 1901.87,683.9 1827.14,758.63 1827.14,784.41 1848.96,806.23 1886.23,806.23 1919.25,839.25 1919.25,880.21 v1(1893.91,905.56)
  Bottom Layer w7: 3503.69,-18.8 3508.2,-14.29 U4.3@3508.2,6.28
  Bottom Layer w10: R189.2@1318,1880.62 1342.38,1880.62 1371,1852 1371,1770 1429.11,1711.89
  Bottom Layer w12: C61.2@3503.69,-44.4 3503.69,-18.8
  Bottom Layer w15: R185.1@1040.9,1747.29 1041.81,1746.38 R182.1@1105,1746.38 ; v1(1105,1711.89) R182.1@1105,1746.38 ; R191.2@1162.52,1746.38 R182.1@1105,1746.38
  Bottom Layer w20: R188.1@879.84,1747.76 R187.1@929.84,1747.76 R186.1@979.84,1747.76 v1(979.84,1706.89) ; v1(1105,1711.89) 1429.11,1711.89 1491,1650 v1(1500,1650) 1501.01,1648.99 R183.1@1501.01,1615 1530,1615 1595.98,1549.02 v1(1595.98,1435.32) ; v1(1845,1371.22) 1846.6,1371.22 1893.91,1323.91 1893.91,1168.66 1812.47,1087.23 1812.47,1035.93 1837.39,1011.01 1921.54,1011.01 1952.25,980.31 1952.25,932.94 1924.86,905.56 v1(1893.91,905.56) ; v1(2313.34,541.23) 2385.69,541.23 2429.28,584.82 2596.38,584.82 2608.13,573.08 2608.13,476.98 2679.57,405.54 3035.22,405.54 v1(3060,380.76) 3094.69,346.08 3094.69,306.56 v1(3089.58,301.46) ; v1(2816.5,278.41) 2934.86,278.41 3010.05,203.22 3121.56,203.22 3149.22,175.57 3253.46,175.57 3293.43,135.6 3293.43,-46.93 3307,-60.5 3365.31,-60.5 3385.58,-40.23 R8.1@3389.52,-40.23 3391.96,-40.23 3393.78,-42.04 3393.78,-56 3407.22,-69.44 3459.72,-69.44 3469.91,-59.25 3469.91,-54.92 v1(3474.83,-50) 3478.88,-45.95 C61.2@3503.69,-45.95
  other v1: 398.65,1859.61 448.65,1859.61
VSYS_TA_3V3_EN: R193.1 U36.3 | length 79.7
  Top Layer w5.3: R193.1@2631.5,99.73 2645.44,99.73 2654.12,108.41 2654.12,131.94 2663.24,141.07 U36.3@2680.31,141.07
VSYS_TA_3V3_PG: R195.1 U36.7 | length 120.1
  Top Layer w5.3: U36.7@2755.12,121.38 2769.91,121.38 2781.5,109.8 2781.5,63.41 2796.24,48.66 R195.1@2817.87,48.66
VSYS_TA_3V3_SLEEP: R194.1 U36.8 | length 88.5
  Top Layer w5.3: U36.8@2755.12,141.07 2771.63,141.07 2782.91,129.79 2809.31,129.79 2817.87,121.22 R194.1@2817.87,103.66
VUSB_5V0: C101.1 C104.1 C105.1 C106.1 C110.1 C187.1 C188.1 C249.1 J10.1 J14.1 L1.2 R91.2 R92.1 R93.1 R94.2 R193.2 R377.1 TP4.1 U18.12 U19.1 U19.2 U19.4 U21.5 U36.2 U47.5 | length 1065.7
  Top Layer w8: 620.41,238.46 620.41,236.56 626.58,230.39 U18.12@626.58,224.61
  Top Layer w10: 1460,623.51 1467.76,615.75 U19.2@1489.52,615.75 ; 1460,645 1469.57,635.43 U19.1@1489.52,635.43 ; U19.4@1489.52,576.38 1489.52,555.69 v1(1490.22,555)
  Top Layer w12: R377.1@373.81,457.26 470.92,457.26 499.34,428.84 499.34,261.38 TP4.1@485.03,247.07 ; v1(602.28,343.25) C101.1@602.28,300.79 602.28,256.58 620.41,238.46 ; R91.2@761.13,113.69 763.55,116.1 v1(763.55,142.11) ; R92.1@819.87,276.93 819.95,277.01 R92.1@819.95,278.31 819.95,303.64 826.98,310.67 v1(844.92,310.67) 889.92,310.67 885.53,306.28 U21.5@885.53,242.76 ; v1(2572.04,118.41) 2572.04,95.44 2607.12,60.36 R193.2@2631.5,60.36 ; 2656.5,160.75 U36.2@2680.31,160.75
  Top Layer w15: v1(621.97,0) 644.6,22.63 R94.2@644.6,59.02 ; R93.1@819.95,120.68 820,120.73 849.75,120.73 v1(849.8,120.78) ; v1(937.3,275.41) C249.1@975.37,275.41 U47.5@975.37,343.6
  other v1: 2514.32,118.41 2543.18,118.41 2600.9,118.41 2514.32,144.53 2543.18,144.53 2572.04,144.53 2600.9,144.53 2543.18,170.66 2514.32,173.39 442.52,189.08 471.18,189.08 499.84,189.08 528.5,189.08 557.17,189.08 442.52,217.74 471.18,217.74 499.84,217.74 528.5,217.74 557.17,217.74 1355,430.04 1390,430.04 1425,430.04 1355,480.04 1390,480.04 1425,480.04 1355,530.04 1390,530.04 1425,530.04 1390,580.04 1425,580.04
XDS_DEBUG_ID4: R138.1 R310.1 U24.63 | length 246.2
  Top Layer w5.3: v1(1014.91,1479.18) R310.1@1014.91,1506.39
  Bottom Layer w5.3: U24.63@873.85,1477.52 873.85,1514.47 881.26,1521.88 974.51,1521.88 990,1506.39 R138.1@1017.94,1506.39 1017.94,1482.21 v1(1014.91,1479.18)
XDS_DEBUG_ID5: R139.1 R309.1 U24.62 | length 236.8
  Top Layer w5.3: R309.1@945.89,1519.68 945.89,1548.95 951.94,1555 v1(971.1,1555)
  Bottom Layer w5.3: U24.62@858.1,1477.52 858.1,1519.33 871.25,1532.48 938.23,1532.48 943.35,1537.6 R139.1@943.35,1555 v1(971.1,1555)
XDS_DEBUG_ID6: R140.1 R308.1 U24.61 | length 207.6
  Top Layer w5.3: R308.1@866.99,1519.68 866.99,1547.34 874.66,1555 v1(915,1555)
  Bottom Layer w5.3: U24.61@842.35,1477.52 842.35,1518.57 878.78,1555 R140.1@889.13,1555 v1(915,1555)
XDS_DEBUG_ID7: R141.1 R261.1 U24.60 | length 146.1
  Top Layer w5.3: R261.1@815,1519.68 815,1554.32 v1(815.68,1555)
  Bottom Layer w5.3: v1(815.68,1555) R141.1@842.24,1555 842.24,1533.73 826.6,1518.09 U24.60@826.6,1477.52
XDS_EMU0: R311.1 U24.42 | length 117.2
  Top Layer w5.3: R311.1@495,1494.68 v1(495,1524.25)
  Bottom Layer w5.3: v1(495,1524.25) 530.73,1524.25 543.14,1511.84 U24.42@543.14,1477.52
XDS_EMU1: R312.1 U24.43 | length 134.9
  Top Layer w5.3: R312.1@622.07,1497.32 v1(622.07,1526.88)
  Bottom Layer w5.3: U24.43@558.89,1477.52 558.89,1514.61 571.16,1526.88 v1(622.07,1526.88)
XDS_PROGSTAZ1: R259.2 U24.4 | length 708.9
  Top Layer w5.3: R259.2@237.71,1563.38 v1(268.02,1563.38)
  SIG 1 w4.75: v1(268.02,1563.38) 268.02,1476.44 360,1384.46 360,1003.7 v1(386.18,977.52)
  Bottom Layer w5.3: U24.4@342.35,977.52 v1(386.18,977.52)
XDS_PROGSTAZ2: R260.2 U24.3 | length 857.2
  Top Layer w5.3: R260.2@242.71,1633.38 v1(273.02,1633.38)
  SIG 1 w4.75: v1(273.02,1633.38) 299.99,1606.41 299.99,1480.75 421.27,1359.47 421.27,1163.73 436.18,1148.82 v1(436.18,977.52)
  Bottom Layer w5.3: U24.3@342.35,961.77 374.31,961.77 378.09,958 416.65,958 v1(436.18,977.52)
XDS_VBUS_DETECT: C135.2 R136.1 R137.2 U24.1 | length 288.7
  Bottom Layer w5.3: R136.1@172.52,999.2 174.49,999.2 204.56,1029.27 204.56,1049.43 C135.2@205,1049.87 ; C135.2@205.06,1049.8 R137.2@251.47,1049.8 251.47,1022.76 302.51,971.71 302.51,936.14 308.38,930.28 U24.1@342.35,930.28
XDSET_1_D_N: J34.2 U24.93 U44.1 U44.10 | length 1271.8
  Top Layer w4.2: J34.2@11.81,1046.6 43.09,1046.6 51.29,1054.79 76.14,1054.79 81.38,1049.55 U44.10@88.56,1049.55 94.8,1049.55 100.05,1054.79 109.01,1054.79 114.25,1049.55 U44.1@121.44,1049.55 128.62,1049.55 133.86,1054.79 146.6,1054.79 v1(160,1041.39)
  SIG 1 w4: v1(160,1041.39) 171.72,1053.11 188.1,1053.11 199.9,1041.31 199.9,935.86 224.28,911.48 377.81,911.48 400.51,888.78 767.1,888.78 795,916.68 795,958.94 776.42,977.52 750.13,977.52 v1(740,987.65)
  Bottom Layer w4.2: v1(740,987.65) 753.4,974.25 917.83,974.25 921.1,977.52 U24.93@948.65,977.52
XDSET_1_D_P: J34.3 U24.94 U44.2 U44.9 | length 1271.6
  Top Layer w4.2: J34.3@11.81,1072.19 42.99,1072.19 51.19,1063.99 76.14,1063.99 81.38,1069.23 U44.9@88.56,1069.23 95.75,1069.23 100.99,1063.99 109.01,1063.99 114.25,1069.23 U44.2@121.44,1069.23 128.62,1069.23 128.62,1068.29 132.92,1063.99 146.6,1063.99 v1(160,1077.39)
  SIG 1 w4: v1(160,1077.39) 160,1068.11 165,1063.11 192.24,1063.11 209.9,1045.45 209.9,940.01 228.42,921.48 381.95,921.48 404.66,898.78 762.96,898.78 785,920.82 785,954.8 772.28,967.52 736.99,967.52 729.55,960.08 729.55,955.61 733.52,951.65 v1(740,951.65)
  Bottom Layer w4.2: v1(740,951.65) 753.4,965.05 917.83,965.05 921.1,961.77 U24.94@948.65,961.77
XDSET_1_ID: J34.4 R130.1 U44.4 U44.7 | length 1353.1
  Top Layer w5.3: J34.4@11.81,1097.78 64.17,1097.78 75,1108.6 U44.7@88.56,1108.6 U44.4@121.44,1108.6 136.73,1108.6 149.79,1121.67 149.79,1147.75 155.7,1153.65 185.77,1153.65 205.14,1134.28 205.14,1099.59 243.04,1061.69 280.18,1061.69 362.27,1143.79 656.53,1143.79 896.1,904.21 v1(1105,904.21)
  Bottom Layer w5.3: R130.1@1075.19,904.21 v1(1105,904.21)
XDSET_1_ID_R: R130.2 U24.95 | length 117.4
  Bottom Layer w5.3: U24.95@948.65,946.02 995.21,946.02 1005,936.23 1005,914.12 1014.91,904.21 R130.2@1035.82,904.21
XDSET_NRST: R143.1 U24.70 | length 78.3
  Bottom Layer w5.3: U24.70@948.65,1339.72 988.86,1339.72 1001.66,1326.93 R143.1@1021.68,1326.93
XDSET_OSC0: C144.2 U24.88 Y3.1 | length 263.2
  Bottom Layer w5.3: U24.88@948.65,1056.26 1001.79,1056.26 1028.04,1082.51 C144.2@1042.72,1082.51 1071.4,1053.83 1128.77,1053.83 1168.63,1093.69 Y3.1@1168.63,1097.63
XDSET_OSC1: C143.2 U24.89 Y3.3 | length 187.7
  Bottom Layer w5.3: U24.89@948.65,1040.51 1002.75,1040.51 1028.31,1014.95 C143.2@1042.72,1014.95 1065.02,1037.24 1079.41,1037.24 Y3.3@1105.64,1011.01
XDSET_RBIAS: R145.2 U24.59 | length 98.3
  Bottom Layer w5.3: R145.2@781.47,1563.62 781.47,1543.52 810.85,1514.13 U24.59@810.85,1477.52
XDSET_TCK: R133.2 U24.35 | length 93.9
  Bottom Layer w5.3: R133.2@430.5,1570.39 432.9,1567.98 U24.35@432.9,1477.52
XDSET_TDI: R135.2 U24.38 | length 139.1
  Bottom Layer w5.3: U24.38@480.15,1477.52 480.15,1511.49 475.48,1516.16 475.48,1532.34 486.91,1543.77 523.66,1543.77 530.5,1550.62 R135.2@530.5,1570.39
XDSET_TMS: R134.2 U24.36 | length 106.1
  Bottom Layer w5.3: U24.36@448.65,1477.52 448.65,1522.74 480.5,1554.59 R134.2@480.5,1570.39
XDSET_UARTA_RX: R129.2 U24.33 | length 147.2
  Bottom Layer w5.3: R129.2@330.5,1570.39 330.5,1541.84 340,1532.34 382.67,1532.34 401.41,1513.6 U24.33@401.41,1477.52
XDSET_UARTA_TX: R131.2 U24.34 | length 108
  Bottom Layer w5.3: R131.2@380.5,1570.39 380.5,1549.5 417.15,1512.85 U24.34@417.15,1477.52
XDSET_VBAT: C142.1 R142.1 U24.68 | length 117.3
  Bottom Layer w5.3: U24.68@948.65,1371.22 990,1371.22 996.29,1364.93 R142.1@1021.68,1364.93 1021.68,1384.93 1017.74,1388.87 C142.1@1017.74,1404.93
XDSET_VREFA: C151.2 C152.2 R144.1 U24.9 U28.1 U28.3 | length 587.1
  Top Layer w5.3: U28.1@228.9,1332 203.89,1332 191.5,1319.61 U28.3@191.5,1237.51 173.18,1237.51 165,1229.33 v1(165,1203.44) 208.88,1159.56 R144.1@257.13,1159.56
  Bottom Layer w5.3: v1(165,1203.44) 165,1185.04 179.89,1170.15 C151.2@210.82,1170.15 C152.2@265.82,1170.15 265.82,1131.18 280.11,1116.89 280.11,1075.03 298.89,1056.26 U24.9@342.35,1056.26
XDSUSB0VBUS: C134.2 R132.1 U24.96 | length 179.6
  Bottom Layer w5.3: U24.96@948.65,930.28 987.32,930.28 992.6,925 992.6,882.15 1010.53,864.22 R132.1@1035.82,864.22 C134.2@1035.82,824.22
pads on no net: 1. 2. 3. 4. ?. D15.1S D15.2S D16.1S D16.2S Designator10. Designator10_1. Designator10_1_1. Designator12. Designator13. Designator14. Designator15. Designator23. Designator23_1. Designator23_1_1. Designator24. Designator24_1. Designator24_1_1. Designator25. Designator25_1. Designator25_1_1. FID1.1 FID2.1 FID3.1 FID4.1 FID5.1 FID6.1 J5.A2 J5.A3 J5.A6 J5.A7 J5.A8 J5.A10 J5.A11 J5.B2 J5.B3 J5.B6 J5.B7 J5.B8 J5.B10 J5.B11 J6.4 J6.5 J6.6 J6.8 J6.9 J6.10 J6.11 J6.12 J6.13 J6.14 J6.15 J6.17 J6.18 J6.19 J6.20 J6.21 J6.22 J6.23 J6.24 J6.29 J6.35 J7. J8. LBL1.0 S2.1 S2.4 SH-J1.0 SH-J2.0 SH-J3.0 SH-J4.0 SH-J5.0 SH-J6.0 SH-J7.0 SH-J8.0 U3.7 U3.8 U3.9 U3.10 U3.17@3198.05,268.7 U6.1 U8.4 U10.2 U10.5 U11.4 U11.9 U12.3@1685,298.04 U12.8@1685,330.91 U13.3@2030,298.56 U13.8@2030,331.44 U14.3@4675,317.68 U14.8@4675,350.55 U15.3@4885.4,317.82 U15.8@4885.4,350.69 U19.0 U20.1 U20.2 U20.3@233.41,476.95 U20.8@266.29,476.95 U20.9 U20.10 U22.14 U22.15 U22.16 U22.17 U22.21 U22.23 U22.24 U24.2 U24.5 U24.6 U24.11 U24.12 U24.13 U24.14 U24.15 U24.18 U24.19 U24.20 U24.21 U24.22 U24.23 U24.24 U24.25 U24.27 U24.29 U24.30 U24.31 U24.32 U24.40 U24.41 U24.44 U24.45 U24.46 U24.49 U24.50 U24.53 U24.54 U24.56 U24.57 U24.65 U24.67 U24.71 U24.72 U24.73 U24.74 U24.75 U24.76 U24.77 U24.78 U24.81 U24.82 U24.83 U24.84 U24.85 U24.86 U24.91 U24.92 U24.102 U24.103 U24.104 U24.105 U24.106 U24.107 U24.108 U24.109 U24.110 U24.111 U24.112 U24.116 U24.117 U24.118 U24.119 U24.120 U24.121 U24.123 U24.124 U24.125 U24.126 U24.127 U24.128 U33.1 U36.4 U36.11@2717.72,115.87 U36.11@2717.72,166.26 U37.14 U37.15 U37.16 U37.17 U37.21 U37.23 U37.24 U38.3@6856.02,638.94 U38.8@6823.14,638.94 U39.3@6855.75,469.6 U39.8@6822.87,469.6 U40.3@6856.02,1588.94 U40.8@6823.14,1588.94 U41.3@6855.75,1459.6 U41.8@6822.87,1459.6 U44.3@121.44,1088.92 U44.5 U44.6 U44.8@88.56,1088.92 U45.7 U45.9@293.89,848.32 U45.9@343.49,848.32 U46.1 U52.15 U52.16

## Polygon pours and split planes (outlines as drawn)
GND on Top Layer "NONET_L-01_P-001" (solid, remove dead copper, pour order 317): -15.19,2149.23 7451.59,2149.23 7550,2050.82 7550,-68.99 7468.99,-150 -18.42,-150 -148.4,-20.02 -148.4,2018.56 -18.05,2148.91
VSYS_5V0_BP_2 on Top Layer "NONET_L-01_P-001" (solid, remove dead copper, pour order 314): 19 vertices, not listed, extent 3820.49,-102.1 5274.41,389.14
VSYS_5V0_BP_1 on Top Layer "NONET_L-01_P-001" (solid, remove dead copper, pour order 311): 1229.76,202.96 1215.28,188.47 1215.28,91.67 1225.96,80.99 1347.29,80.99 1410.47,144.17 1479.37,144.17 1498.79,163.59 1498.79,218.98 1470.95,246.81 1372.11,246.81 1328.26,202.96
GND on Top Layer "NONET_L-01_P-001" (solid, remove dead copper, pour order 290): 3631.44,441.1 3648.44,441.1 3653.56,435.98 3653.56,388.63 3637.64,372.71 3637.64,365.56 3633.73,361.65 3622.27,361.65 3615.52,368.39 3615.52,376.35 3616.33,376.35 3626.99,387.01 3626.99,437.32 3630.9,441.24
VBUS_XDS_5V0 on Top Layer "TOP_LAYER_VBUS_XDS_5V0_P297" (solid, remove dead copper, pour order 297): 61,1008.78 75.08,1022.85 143.71,1022.85 156.21,1010.35 156.21,833.54 179.38,810.37 304.5,810.37 311.8,803.06 311.8,765.37 301.43,755 99.69,755 61,793.69
GND_XDS on Top Layer "Top Layer-GND_XDS" (solid, pour order 124): 191.8,820.68 439.58,820.68 439.58,885.94 190.03,885.94 184.13,880.03 184.13,827 188.86,822.27
SHIELD4 on Top Layer "Bottom Layer-SHIELD4" (solid, remove dead copper, pour order 295): 23 vertices, not listed, extent -140.16,878.11 75,1344.48
GND on Top Layer "Top Layer-GND 10" (solid, pour order 233): 3367.52,815.34 3300.35,815.34 3258.32,773.3 3057.35,773.3 3020,735.95 3020,607.86 3099.26,528.6 3241.12,528.6 3436.2,723.68 3436.2,791.78 3409.17,818.81 3370,818.81
VUSB_5V0 on Top Layer "Top Layer-VSYS_5V0 5" (solid, pour order 126): 2690.84,168.41 2656.5,168.41 2641.5,183.41 2501.5,183.41 2501.5,107.1 2603.9,107.1 2630.22,133.41 2641.5,133.41 2657.32,149.24 2691.33,149.24 2695.5,153.41 2695.5,164.3 2690.84,168.97
VPP_AM263_1V7 on Top Layer "NONET_L-01_P-001" (solid, remove dead copper, pour order 288): 2412.01,399.34 2397.33,384.61 2365.28,384.61 2365.28,453.14 2443.55,453.14 2443.55,399.34
VSYS_5V0 on Top Layer "NONET_L-01_P-001" (solid, remove dead copper, pour order 287): 2322.91,385.33 2322.91,451.01 2276.35,451.01 2276.35,385.33
GND on Top Layer "Top Layer-GND" (solid, pour order 286): 17 vertices, not listed, extent 1305,500 1697.43,806.85
VSYS_5V0 on Top Layer "Top Layer-VSYS_5V0" (solid, pour order 285): 1552.92,683.18 1552.92,607.91 1654.17,607.91 1654.17,505.43 1799.39,505.43 1799.39,723.62 1716.75,723.62 1676.3,683.18
SHIELD1 on Top Layer "NONET_L-01_P-001" (solid, remove dead copper, pour order 274): 30 vertices, not listed, extent -144.23,-103.9 263,582.61
VUSB_5V0 on Top Layer "Top Layer-VUSB_5V0" (solid, pour order 268): 1349.34,417.25 1342.79,423.79 1342.79,665.05 1360,683.18 1500,683.18 1500,607.91 1472.08,607.91 1445,580.83 1445,425.1 1437.03,417.25
VSD_3V3 on Top Layer "NONET_L-01_P-001" (solid, remove dead copper, pour order 273): 18 vertices, not listed, extent 895.06,452.36 1058.54,543.7
GND on Top Layer "NONET_L-01_P-001" (solid, remove dead copper, pour order 271): 325.65,94.42 535.22,94.42 546.98,82.66 546.98,-79.86 530.42,-96.43 298.83,-96.43 291.97,-89.57 291.97,60.74
VUSB_5V0 on Top Layer "NONET_L-01_P-001" (solid, remove dead copper, pour order 270): 347.08,200.87 406.21,200.87 469.55,264.21 553.5,264.21 570.7,247.02 570.7,136.37 548.02,113.69 353.85,113.69 346.85,120.68 346.85,168.85
GND on Top Layer "NONET_L-01_P-001" (solid, remove dead copper, pour order 267): 336.6,418.9 472.88,418.9 472.88,300.26 399.52,226.9 336.6,226.9
VBUS_TYPEC_5V0 on Top Layer "Top Layer-VBUS_TYPEC_5V0" (solid, pour order 264): 182.59,370.32 210.11,397.83 298.96,397.83 316.85,379.94 316.85,130.55 311.8,125.5 237.48,125.5 209.93,153.05 210,247.7 182.59,275.11
SHIELD3 on Top Layer "Top Layer-SHIELD3" (solid, pour order 100): 19 vertices, not listed, extent 7060,1112.87 7500,2015
VSYS_5V0 on Top Layer "Top Layer-VSYS_5V0 3" (solid, pour order 50): 2580.81,1303.13 2591.67,1314 2591.2,1330.45 2641.99,1381.23 2641.99,1397.41 2648.1,1403.53 2680.96,1403.53 2680.96,1424.47 2361.67,1424.47 2361.67,1303.13
GND on Top Layer "Top Layer-GND 9" (solid, pour order 231): 3495.4,801.33 3835,801.33 3835,1140 3510.4,1140 3495.4,1125
VDD_ETH2_1V1_FILT on Top Layer "Top Layer-VDD_ETH2_1V1_FILT" (solid, pour order 257): 6052.73,1325.21 6052.73,1255 6282.19,1255 6282.19,1325.21
VDD_ETH1_1V1_FILT on Top Layer "Top Layer-VDD_ETH1_1V1_FILT" (solid, remove dead copper, pour order 259): 6052.73,1186.32 6052.73,1126.79 6285,1126.79 6285,1186.32
VSYS_3V3 on Top Layer "Top Layer-VSYS_3V3 1" (solid, remove dead copper, pour order 263): 510,1975 510,1953.92 480.73,1924.65 480.73,1849.25 524.75,1849.25 524.75,1975
VDD_ETH2_2V5_FILT on Top Layer "Top Layer-VDD_ETH2_2V5_FILT" (solid, remove dead copper, pour order 255): 31 vertices, not listed, extent 6050,1011.86 6705,1620
VDD_ETH1_2V5_FILT on Top Layer "Top Layer-VDD_ETH1_2V5_FILT" (solid, remove dead copper, pour order 253): 26 vertices, not listed, extent 5980,491.19 6705,843.7
GND on Top Layer "Top Layer-GND 2" (solid, pour order 74): 5421.46,1503.41 5421.46,1639.19 5970,1639.19 5970,1521.81 5804.23,1521.81 5779.53,1497.1 5681.61,1497.1 5681.61,1370.09 5714.09,1370.09 5725,1359.19 5725,1325.21 5795,1325.21 5795,1274.19 5615,1274.19 5615,1503.41
VSYS_5V0 on Top Layer "Top Layer-VSYS_5V0 1" (solid, pour order 78): 5599.01,1482.33 5599.01,1409.19 5425,1409.19 5425,1359.19 5340,1359.19 5340,1482.33
VSYS_5V0 on Top Layer "Top Layer-VSYS_5V0 2" (solid, pour order 62): 5599.01,1066.57 5599.01,990 5425,990 5425,940 5340,940 5340,1066.57
NetR256_2 on Top Layer "Top Layer-NetR256_2" (solid, pour order 176): 4378.38,679.74 4450.43,679.74 4450.43,753.1 4378.38,753.1
VSYS_TA_3V3 on Top Layer "Top Layer-VSYS_TA_3V3" (solid, pour order 136): 355,1880 461.13,1880 461.13,1790 355,1790
TPS62913_2_SW on Top Layer "Top Layer-TPS62913_2_SW" (solid, pour order 54): 2741.67,1432.62 2771.91,1402.38 2940,1402.38 2940,1462.62 2766.67,1462.62 2741.67,1437.62
GND on Top Layer "Top Layer-GND 4" (solid, pour order 48): 2677.72,1727.62 2446.67,1727.62 2446.67,1479.58 2607.41,1479.58 2639.37,1447.62 2677.72,1447.62
SHIELD2 on Top Layer "Top Layer-SHIELD2" (solid, pour order 98): 7220.4,990 7220.4,1028.69 7135,1028.69 7135,900 7100,900 7100,137.87 7115,122.87 7211.33,122.87 7355,266.54 7378.25,289.79 7500,289.79 7500,703.43 7385,703.43 7320,768.43 7320,990
GND on Top Layer "Top Layer-GND 6" (solid, pour order 138): 339.87,1790 228.92,1790 228.92,1880 340.05,1880 340.05,1790.81
GND on Top Layer "Top Layer-GND 7" (solid, pour order 128): 17 vertices, not listed, extent 2501.5,63.3 2768.5,358.23
VSYS_TA_3V3 on Top Layer "Top Layer-VSYS_TA_3V3 1" (solid, pour order 132): 2749.14,273.75 2738.8,263.41 2738.8,219.78 2745,213.58 2745,179.96 2764.84,179.96 2793.21,208.33 2876.5,208.33 2876.5,357.66 2749.14,357.66
NetL4_1 on Top Layer "Top Layer-NetL4_1" (solid, pour order 130): 2776.12,178.21 2768.5,170.59 2748.15,170.59 2745,167.44 2745,156.79 2749.14,152.65 2778.49,152.65 2791.5,139.64 2880.89,139.64 2886.5,145.25 2886.5,173.21 2881.5,178.21
VDD_XDS3V3 on Top Layer "Top Layer-VDD_XDS3V3" (solid, pour order 122): 488.15,752.27 488.15,805.61 331.48,805.61 331.48,752.27
VDD_ETH_1V1 on Top Layer "Top Layer-VDD_ETH_1V1" (solid, pour order 76): 6030,1130.86 5985,1130.86 5985,1244.59 5951.86,1277.72 5860,1277.72 5860,1380.63 5846.44,1394.19 5777.62,1394.19 5762.62,1409.19 5699.18,1409.19 5699.18,1481.81 5785,1481.81 5805,1461.81 6030,1461.81
GND on Top Layer "Top Layer-GND 3" (solid, pour order 68): 17 vertices, not listed, extent 5398.66,855 5965,1220
VDD_ETH_2V5 on Top Layer "Top Layer-VDD_ETH_2V5" (solid, pour order 64): 21 vertices, not listed, extent 5699.18,797.13 6025,1066.93
VSYS_3V3 on Top Layer "Top Layer-VSYS_3V3" (solid, pour order 52): 2701.04,1727.62 2701.04,1447.62 2730.55,1447.62 2775.55,1492.62 2945,1492.62 2945,1727.62
GND on Top Layer "Top Layer-GND 5" (solid, pour order 40): 2316.04,1095 2085,1095 2085,846.97 2245.73,846.97 2277.7,815 2316.04,815
VSYS_5V0 on Top Layer "Top Layer-VSYS_5V0 4" (solid, pour order 38): 2219.14,670.52 2230,681.38 2229.53,697.83 2280.32,748.61 2280.31,764.8 2286.43,770.91 2319.29,770.91 2319.29,791.85 2000,791.85 2000,670.52
VDD_AM263_1V2 on Top Layer "Top Layer-VDD_AM263_1V2" (solid, pour order 36): 2339.37,1090 2339.37,815 2374.22,815 2419.22,860 2581.93,860 2581.93,1090
TPS62913_1_SW on Top Layer "Top Layer-TPS62913_1_SW" (solid, pour order 34): 2380,800 2410.24,769.76 2580,769.76 2580,830 2405,830 2380,805
GND on Bottom Layer "NONET_L-01_P-001" (solid, remove dead copper, pour order 318): -15.19,2149.23 7451.59,2149.23 7550,2050.82 7550,-68.99 7468.99,-150 -18.42,-150 -148.4,-20.02 -148.4,2056.43 -60.67,2144.16
VUSB_5V0 on Bottom Layer "Bottom Layer-VUSB_5V0" (solid, pour order 20): 25 vertices, not listed, extent 421.27,-124 2643.29,656.7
